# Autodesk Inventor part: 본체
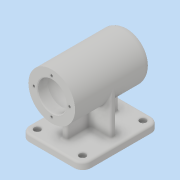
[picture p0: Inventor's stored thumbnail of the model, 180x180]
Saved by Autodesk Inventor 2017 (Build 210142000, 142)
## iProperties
Part Number: 본체
Material: 일반
Document SubType Name: Modeling
Designer: mrc
Density: 1 g/cm^3
Appearance: 기본값
Author: mrc
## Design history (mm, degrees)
sketch "스케치2"
  geometry: L1 (0, 56)-(0, -56); L2 (34, 46)-(34, -56); L3 (34, -56)-(21, -56); L4 (21, -56)-(21, -41); L5 (21, -41)-(24, -41); L6 (24, -41)-(24, 13); L7 (24, 13)-(21, 13); L8 (21, 13)-(21, 25); L9 (21, 25)-(17.5, 25); L10 (17.5, 25)-(17.5, 43); L11 (17.5, 43)-(16, 43); L12 (16, 43)-(16, 47); L13 (16, 47)-(10.5, 47); L14 (10.5, 47)-(10.5, 50); L15 (10.5, 50)-(0, 50); L16 (24, 56)-(0, 56); A1 r 10 centre (24, 46) between (34, 46) and (24, 56); 2 further points
  constraints: 32 end point, 7 perpendicular, 4 vertical, 3 horizontal, 2 point on circle, 2 tangent, 1 centre point, 1 coincident, 1 horizontal alignment, 1 midpoint, 1 parallel, 1 point on line
  dimensions: "d3" = 68 diameter of L2 L1; "d5" = 42 diameter of L4 L1; "d6" = 48 diameter of L6 L1; "d7" = 42 diameter of L8 L1; "d9" = 15 distance between parallel lines of L3 L5; "d10" = 54 distance from line of L4.end L7; "d11" = 112 distance of L1.start L1.end; "d12" = 12 distance of L7.end L8.end; "d13" = 18 distance of L9.end L10.end; "d14" = 35 diameter of L10 L1; "d15" = 32 diameter of L12 L1; "d17" = 4 distance between parallel lines of L11 L13; "d18" = 3 distance of L13.end L14.end; "d19" = 21 diameter of L14 L1; "d20" = 10 radius of A1
revolve "회전1" sketch "스케치2" stored, may be unused: angle "d21" = 90 deg
sketch "스케치3"
  geometry: L1 (45, -64)-(-45, -64); L2 (-45, -64)-(-45, -74); L3 (-45, -74)-(45, -74); L4 (45, -74)-(45, -64); 2 further points
  constraints: 8 end point, 2 parallel, 1 horizontal, 1 midpoint, 1 perpendicular, 1 vertical alignment
  dimensions: "d22" = 10 distance of L1.end L2.end; "d23" = 74 distance from line of L3 point (0, 0); "d24" = 90 distance of L2.end L3.end
extrude "돌출2" join sketch "스케치3" stored distance "d25" = 112; taper "d26" = 0 deg
sketch "스케치4"
  geometry: L1 (79, 60)-(11, 60); L2 (11, 60)-(11, 52); L3 (11, 52)-(79, 52); L4 (79, 52)-(79, 60); L5 (79, 60)-(11, 52); L6 (11, 60)-(79, 52); L7 (49, 94)-(41, 94); L8 (41, 94)-(41, 18); L9 (41, 18)-(49, 18); L10 (49, 18)-(49, 94); L11 (49, 94)-(41, 18); L12 (41, 94)-(49, 18); L13 (0, 112)-(0, 0) reference; L14 (0, 0)-(90, 0) reference; 1 further point
  constraints: 24 end point, 4 midpoint, 4 parallel, 2 horizontal, 2 perpendicular
  dimensions: "d27" = 8 distance of L8.end L9.end; "d28" = 8 distance of L1.end L2.end; "d30" = 18 distance between parallel lines of L14 L9; "d95" = 68 distance between parallel lines of L2 L4
extrude "돌출3" join sketch "스케치4" stored distance "d31" = 10; taper "d32" = 0 deg
sketch "스케치5"
  geometry: 2 further points
  constraints: 1 vertical alignment
  dimensions: "d33" = 26 distance of point (0, 0) point (0, 26)
hole "구멍1" sketch "스케치5" at (0, 26) diameter "d34" = 3.242; stored, may be unused: countersink angle "d38" = 90 deg, drill point angle "d40" = 118 deg; dims "d35" = 8, "d36" = 4, "d37" = 2, "d39" = 11
fillet "모깎기1" dims "d44" = 12
hole "구멍2" diameter "d47" = 5.5; stored, may be unused: countersink angle "d51" = 90 deg, drill point angle "d53" = 0 deg; dims "d45" = 10, "d46" = 10, "d48" = 8, "d49" = 9.5, "d50" = 5.4, "d52" = 11
hole "구멍3" diameter "d56" = 5.5; stored, may be unused: countersink angle "d60" = 90 deg, drill point angle "d62" = 0 deg; dims "d54" = 10, "d55" = 10, "d57" = 8, "d58" = 9.5, "d59" = 5.4, "d61" = 11
hole "구멍4" diameter "d65" = 5.5; stored, may be unused: countersink angle "d69" = 90 deg, drill point angle "d71" = 0 deg; dims "d63" = 10, "d64" = 10, "d66" = 8, "d67" = 9.5, "d68" = 5.4, "d70" = 11
hole "구멍5" diameter "d74" = 5.5; stored, may be unused: countersink angle "d78" = 90 deg, drill point angle "d80" = 0 deg; dims "d72" = 10, "d73" = 10, "d75" = 8, "d76" = 9.5, "d77" = 5.4, "d79" = 11
sketch "스케치6"
  geometry: L1 (0, 10)-(88, 10) reference; L2 (100, 0)-(100, 10) reference; L3 (88, 0)-(0, 0) reference; 2 further points
  constraints: 1 other
  dimensions: "d82" = 56 distance from line of L2 point (44, 3); "d83" = 3 distance from line of L3 point (44, 3)
feature "엠보싱1" sketch "스케치6" dims "d3" = 68, "d5" = 42, "d6" = 48, "d7" = 42, "d9" = 15, "d10" = 54, "d11" = 112, "d12" = 12, "d13" = 18, "d14" = 35, "d15" = 32, "d17" = 4, "d18" = 3, "d19" = 21, "d20" = 10, "d84" = 0.5, "d85" = 0
fillet "모깎기2" dims "d86" = 0.3
fillet "모깎기3" dims "d87" = 3
fillet "모깎기4" dims "d88" = 3
fillet "모깎기5" dims "d89" = 3
fillet "모깎기6" dims "d90" = 3
chamfer "모따기1" distance "d91" = 1; stored, may be unused: second distance "d92" = 2, angle "d93" = 45 deg
fillet "모깎기7" dims "d94" = 3
node "솔리드2"
pattern_circular "원형 패턴1" dims angle "d42" = 360 deg
